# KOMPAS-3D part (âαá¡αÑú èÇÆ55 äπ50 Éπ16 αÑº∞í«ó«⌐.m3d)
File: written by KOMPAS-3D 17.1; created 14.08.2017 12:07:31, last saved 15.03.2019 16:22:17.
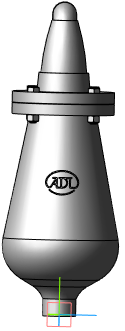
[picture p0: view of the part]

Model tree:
1. Операция без истории:3  (labels: Сталь 20  ГОСТ 1050-2013)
